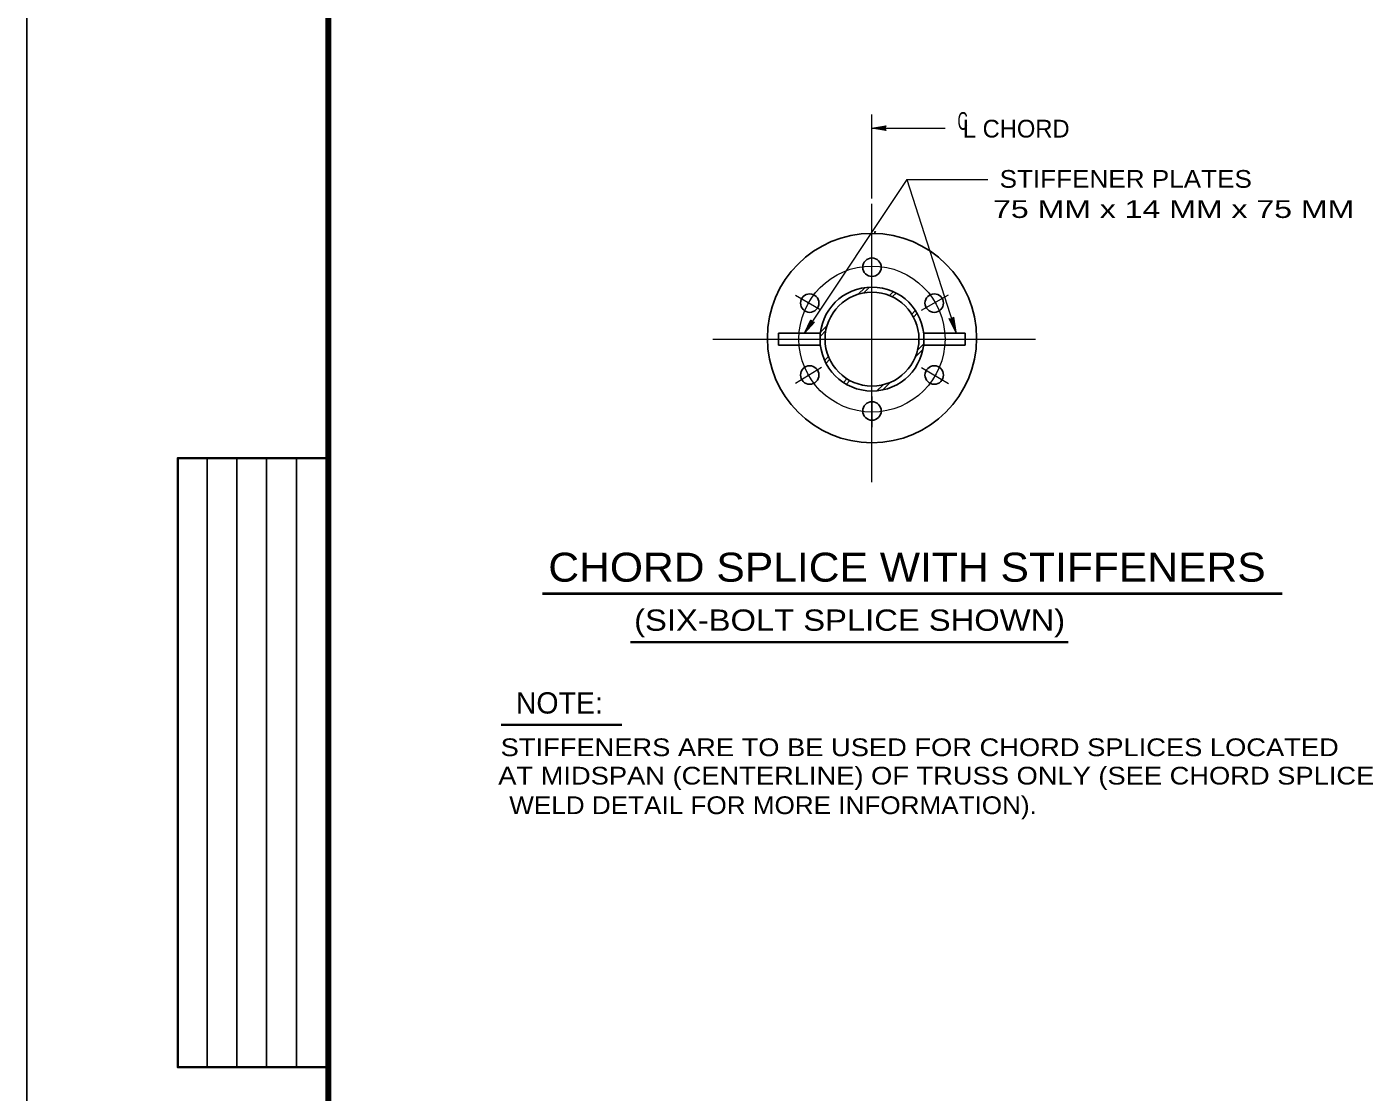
# Model space of a CAD drawing. Extents: x 312601.858 to 312602.699, y 144420.109 to 144420.704.
# Drawn here: x 312601.8578 to 312602.0855, y 144420.3433 to 144420.5234 of the extents above; entities that cross this region are included whole.
import ezdxf
from ezdxf.enums import TextEntityAlignment as Align

# ---------------------------------------------------------------- set-up
doc = ezdxf.new("R2010")
doc.units = 0
doc.header["$LTSCALE"] = 0.0012
doc.linetypes.add('DOT_DASHED', pattern=[7.7, 5, -1.2, 0.3, -1.2])
for name, color, linetype, lineweight in [('1', 7, 'Continuous', 25), ('2', 7, 'Continuous', 13), ('39', 7, 'Continuous', 13), ('60', 7, 'Continuous', 25)]:
    doc.layers.add(name, color=color, linetype=linetype, lineweight=lineweight)

msp = doc.modelspace()

# ---------------------------------------------------------------- hatches: boundary and pattern name
at = {"layer": '39'}
for points in [[(312602.0029, 144420.5063), (312602.0031, 144420.5059), (312602.0007, 144420.5063), (312602.0031, 144420.5067)], [(312601.9906, 144420.4735), (312601.991, 144420.4735), (312601.9893, 144420.4716), (312601.9904, 144420.4739)], [(312601.9906, 144420.4735), (312601.991, 144420.4735), (312601.9893, 144420.4716), (312601.9904, 144420.4739)], [(312602.0142, 144420.474), (312602.0145, 144420.4743), (312602.0149, 144420.4718), (312602.0138, 144420.4741)]]:
    msp.add_hatch(color=256, dxfattribs=at).paths.add_polyline_path(points)

# ---------------------------------------------------------------- linework, layer by layer
at = {"layer": '1', "lineweight": 13}
for p, q in [((312602.0007, 144420.4944), (312602.0007, 144420.5086)), ((312602.0007, 144420.5063), (312602.0131, 144420.5063)), ((312602.0066, 144420.4976), (312601.9893, 144420.4716)), ((312602.0066, 144420.4976), (312602.0203, 144420.4976)), ((312602.0066, 144420.4976), (312602.0149, 144420.4718))]:
    msp.add_line(p, q, dxfattribs=at)
at = {"layer": '1', "linetype": 'DOT_DASHED', "lineweight": 13}
for p, q in [((312602.0007, 144420.4464), (312602.0007, 144420.4935)), ((312602.0007, 144420.4803), (312602.0007, 144420.4856)), ((312601.9921, 144420.4755), (312601.9878, 144420.478)), ((312602.0091, 144420.4755), (312602.0137, 144420.4781)), ((312601.9738, 144420.4706), (312602.0284, 144420.4706)), ((312601.9922, 144420.4658), (312601.9878, 144420.4631)), ((312602.0091, 144420.4658), (312602.0137, 144420.4631)), ((312602.0007, 144420.4609), (312602.0007, 144420.4557))]:
    msp.add_line(p, q, dxfattribs=at)
at = {"layer": '1'}
for p, q in [((312601.9849, 144420.4716), (312601.9849, 144420.4696)), ((312601.992, 144420.4716), (312601.9849, 144420.4716)), ((312602.0095, 144420.4716), (312602.0165, 144420.4716)), ((312602.0165, 144420.4716), (312602.0165, 144420.4696)), ((312601.9849, 144420.4696), (312601.992, 144420.4696)), ((312602.0095, 144420.4696), (312602.0165, 144420.4696))]:
    msp.add_line(p, q, dxfattribs=at)
for centre, radius in [((312602.00073, 144420.47079), 0.017693), ((312602.00073, 144420.482775), 0.00156), ((312601.990203, 144420.476698), 0.00156), ((312602.00073, 144420.47062), 0.008788), ((312602.00073, 144420.47062), 0.007942), ((312602.011257, 144420.476698), 0.00156), ((312601.990203, 144420.464543), 0.00156), ((312602.011257, 144420.464543), 0.00156), ((312602.00073, 144420.458465), 0.00156)]:
    msp.add_circle(centre, radius, dxfattribs=at)
at = {"layer": '1', "linetype": 'DOT_DASHED', "lineweight": 13}
msp.add_circle((312602.00073, 144420.47062), 0.012354, dxfattribs=at)
at = {"layer": '2'}
for p, q in [((312601.9984, 144420.4782), (312601.9995, 144420.4793)), ((312601.9993, 144420.4784), (312602.0003, 144420.4794)), ((312602.0037, 144420.478), (312602.0043, 144420.4786)), ((312602.0042, 144420.4778), (312602.0048, 144420.4784)), ((312602.0075, 144420.4749), (312602.0081, 144420.4755)), ((312602.0078, 144420.4744), (312602.0084, 144420.475)), ((312601.992, 144420.4718), (312601.9932, 144420.473)), ((312601.992, 144420.4711), (312601.993, 144420.4721)), ((312602.0081, 144420.4676), (312602.0093, 144420.4688)), ((312602.0084, 144420.4687), (312602.0095, 144420.4698)), ((312601.9927, 144420.467), (312601.9934, 144420.4677)), ((312601.9929, 144420.4665), (312601.9936, 144420.4672)), ((312601.9959, 144420.4633), (312601.9965, 144420.4639)), ((312601.9964, 144420.463), (312601.997, 144420.4636)), ((312602.0015, 144420.4618), (312602.0026, 144420.4629)), ((312602.0025, 144420.462), (312602.0038, 144420.4633))]:
    msp.add_line(p, q, dxfattribs=at)
at = {"layer": '2', "lineweight": 40}
msp.add_line((312601.945, 144420.4276), (312602.0701, 144420.4276), dxfattribs=at)
at = {"layer": '2', "lineweight": 35}
for p, q in [((312601.9599, 144420.4194), (312602.0339, 144420.4194)), ((312601.938, 144420.4054), (312601.9584, 144420.4054))]:
    msp.add_line(p, q, dxfattribs=at)
at = {"layer": '2'}
msp.add_lwpolyline([(312602.0013, 144420.4888), (312602.0012, 144420.4886), (312602.0012, 144420.4888), (312602.0012, 144420.4888)], close=True, dxfattribs=at)
at = {"layer": '39', "lineweight": 25}
msp.add_line((312601.8578, 144420.1095), (312601.8578, 144420.7035), dxfattribs=at)
at = {"layer": '39', "lineweight": 158}
msp.add_line((312601.9088, 144420.1247), (312601.9088, 144420.6645), dxfattribs=at)
at = {"layer": '39'}
for points in [[(312602.0029, 144420.5063), (312602.0031, 144420.5059), (312602.0007, 144420.5063), (312602.0031, 144420.5067)], [(312601.9906, 144420.4735), (312601.991, 144420.4735), (312601.9893, 144420.4716), (312601.9904, 144420.4739)], [(312601.9906, 144420.4735), (312601.991, 144420.4735), (312601.9893, 144420.4716), (312601.9904, 144420.4739)], [(312602.0142, 144420.474), (312602.0145, 144420.4743), (312602.0149, 144420.4718), (312602.0138, 144420.4741)]]:
    msp.add_lwpolyline(points, close=True, dxfattribs=at)
at = {"layer": '60'}
for p, q in [((312601.8883, 144420.3475), (312601.8883, 144420.4505)), ((312601.8933, 144420.3475), (312601.8933, 144420.4505)), ((312601.8983, 144420.3475), (312601.8983, 144420.4505)), ((312601.9034, 144420.3475), (312601.9034, 144420.4505))]:
    msp.add_line(p, q, dxfattribs=at)
at = {"layer": '60', "lineweight": 35}
msp.add_lwpolyline([(312601.9084, 144420.3475), (312601.8833, 144420.3475), (312601.8833, 144420.4505), (312601.9084, 144420.4505)], dxfattribs=at)

# ---------------------------------------------------------------- texts
at = {"layer": '2', "width": 0.6}
msp.add_text('C', height=0.003, dxfattribs=at).set_placement((312602.0152, 144420.506))
at = {"layer": '2'}
msp.add_text('L CHORD', height=0.003, dxfattribs=at).set_placement((312602.0161, 144420.5047))
for s, height, width, p in [('STIFFENER PLATES', 0.003, 1.1, (312602.04365, 144420.4962)), ('75 MM x 14 MM x 75 MM', 0.003, 1.35, (312602.05175, 144420.4911)), ('CHORD SPLICE WITH STIFFENERS', 0.0049, 1.1, (312602.00665, 144420.4296)), ('(SIX-BOLT SPLICE SHOWN)', 0.0036, 1.15, (312601.99695, 144420.4213)), ('STIFFENERS ARE TO BE USED FOR CHORD SPLICES LOCATED', 0.003, 1.15, (312602.0088, 144420.4001)), ('AT MIDSPAN (CENTERLINE) OF TRUSS ONLY (SEE CHORD SPLICE', 0.003, 1.15, (312602.0116, 144420.3953)), ('WELD DETAIL FOR MORE INFORMATION).', 0.003, 1.1, (312601.984, 144420.3903))]:
    msp.add_text(s, height=height, dxfattribs=dict(at, width=width)).set_placement(p, align=Align.CENTER)
msp.add_text('NOTE:', height=0.0036, dxfattribs=at).set_placement((312601.94785, 144420.4073), align=Align.CENTER)

doc.saveas('drawing.dxf')
